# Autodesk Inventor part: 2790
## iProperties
Author: Administrator
Shininess: 64.0
Angle Display Precision: 2
Document Length Units: 11272
Document Angle Units: 11286
Document Time Units: 11279
Document Mass Units: 11290
Document Length Units Precision: 3
Document Angle Units Precision: 2
Compacted: True
PropertySet Name: _Private Model Information
Created: 2002-03
Part Number: 2790
Material: ASTM A36 HRS
Document SubType Name: Modeling
Designer: Administrator
Control State: 0
Master: False
Checked Out: False
PropertySet Name: Design Tracking Control
Density: 0.0
Volumn: 0.0
Area: 0.0
PropertySet Name: Model Information
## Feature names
1. Revolution1
